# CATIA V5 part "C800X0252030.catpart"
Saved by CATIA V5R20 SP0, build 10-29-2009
Part number: C800X0252030
Source: Unknown
Property "A": "34"
Property "ARTICLENO": "C800X0252030"
Property "B": "16"
Property "BOMINFO": "C800X0252030"
Property "C": "57"
Property "CA": "C800X0252030"
Property "D1": "50"
Property "DES": "ROTATING EYEBOLT WITH RING Ton 2,5 M20x30"
Property "E": "61"
Property "H": "131"
Property "L": "30"
Property "LINA": "C800X0252030"
Property "NB": "C800X0252030"
Property "NBSYN": "$CODE."
Property "NN": "C800X"
Property "NT": "Rotating eyebolt with ring"
Property "SIZE": "M20"
Property "SUPPLIER": "CF"
Property "SW": "40"
Property "WEIGHT": "1050"
Property "WLL": "2.50"
Bounding box of the stored display mesh (mm): x -33 to 33, y -30 to 146.819, z -25 to 25
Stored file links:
  C:\Users\Utente\Desktop\3D files 800X\C800X0252030.catpart

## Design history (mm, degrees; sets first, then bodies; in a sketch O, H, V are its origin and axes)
Body1 "Geometry.1" (main body)
  Solid1 "C800X0252030.catpart": solid without history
